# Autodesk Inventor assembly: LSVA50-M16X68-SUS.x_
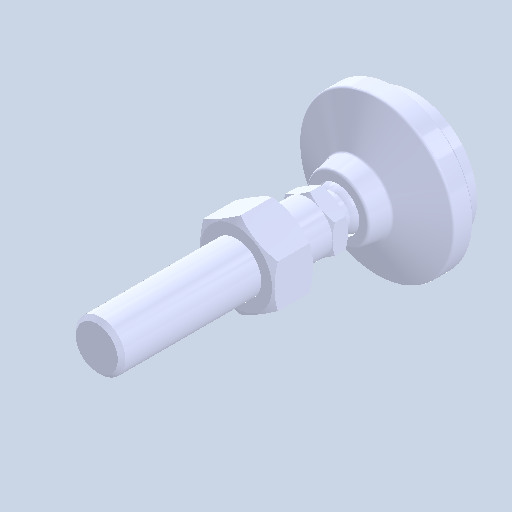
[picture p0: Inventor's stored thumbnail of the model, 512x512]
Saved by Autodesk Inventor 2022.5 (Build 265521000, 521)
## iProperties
Created: 2024-08
Part Number: LSVA50-M16X68-SUS.x_
Document SubType Name: Assembly
Designer: ImaoCorp
Author: ImaoCorp
Sending System: SOLIDWORKS 2022-2022290
MC: AMD64
MC_MODEL: Intel64 Family 6 Model 60 Stepping 3, GenuineIntel
OS: Windows_NT
FRU: Parasolid Version 33.1, build 260,  4-25-2022
FORMAT: text
GUISE: transmit
KEY: FILELSVA50-M16X68-SUS.x_t
DATE: Fri Aug 23 16:08:47 2024
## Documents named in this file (4)
- X:\14_SW2022-Inv2022\06_2024-10新製品(SME)\ELS_データ\l\lsva50-m16x68-sus\LSVA50-M16X68-SUS.x_.iam
- X:\14_SW2022-Inv2022\06_2024-10新製品(SME)\ELS_データ\l\lsva50-m16x68-sus\LSVA50-M16X68-SUS_01.ipt
- X:\14_SW2022-Inv2022\06_2024-10新製品(SME)\ELS_データ\l\lsva50-m16x68-sus\LSVA50-M16X68-SUS_02.ipt
- X:\14_SW2022-Inv2022\06_2024-10新製品(SME)\ELS_データ\l\lsva50-m16x68-sus\LSVA50-M16X68-SUS_03.ipt
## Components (3 placed, 3 different names)
1. LSVA50-M16X68-SUS_01
2. LSVA50-M16X68-SUS_02
3. LSVA50-M16X68-SUS_03
